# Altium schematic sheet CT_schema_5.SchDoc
size 295 x 165 mm
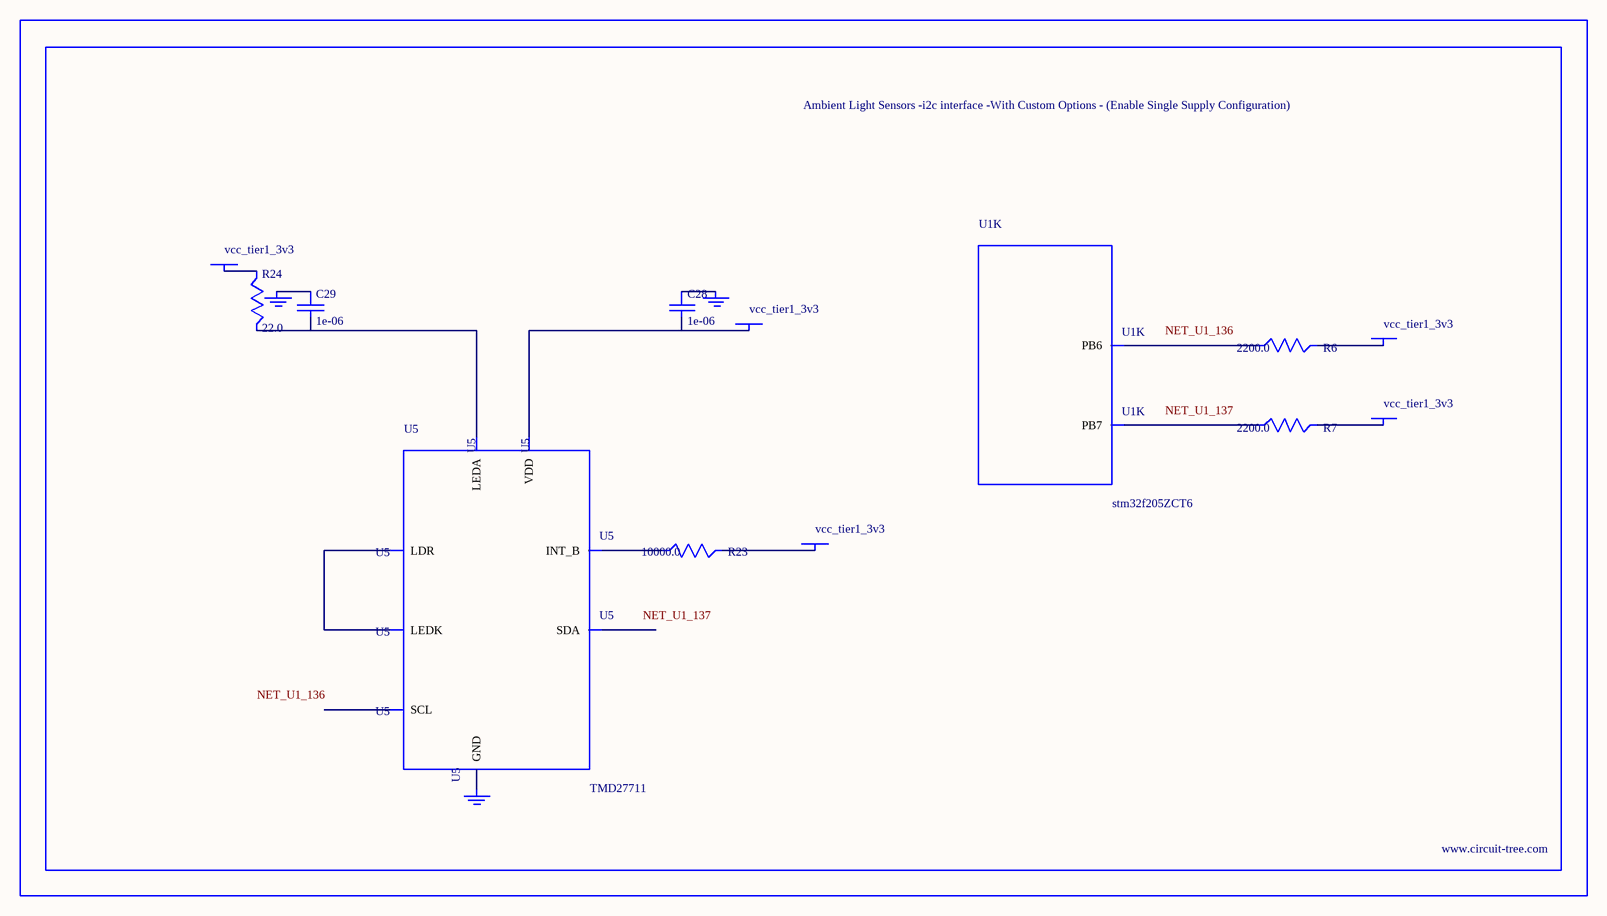
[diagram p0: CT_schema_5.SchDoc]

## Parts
BORDER4  (no value)
C28  1e-06  [C0603]
C29  1e-06  [C0603]
GND_INSTANCE_4_0  (no value)
GND_INSTANCE_4_1  (no value)
GND_INSTANCE_4_2  (no value)
POWER_INSTANCE_4_0  vcc_tier1_3v3
POWER_INSTANCE_4_1  vcc_tier1_3v3
POWER_INSTANCE_4_2  vcc_tier1_3v3
POWER_INSTANCE_4_3  vcc_tier1_3v3
POWER_INSTANCE_4_4  vcc_tier1_3v3
R6  2200.0  [R0603]
R7  2200.0  [R0603]
R23  10000.0  [R0603]
R24  22.0  [R0603]
U1  stm32f205ZCT6  [LQFP144]  (part K of 12)
U5  TMD27711  [SMD-8]

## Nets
NetC28_1: C28.1 GND_INSTANCE_4_0.0(GND)
NetC28_2: C28.2 POWER_INSTANCE_4_0.0(PWR) U5.1(VDD)
NetC29_1: C29.1 GND_INSTANCE_4_1.0(GND)
NetC29_2: C29.2 R24.2 U5.4(LEDA)
NetGND_INSTANCE_4_2_0: GND_INSTANCE_4_2.0(GND) U5.3(GND)
NetPOWER_INSTANCE_4_1_0: POWER_INSTANCE_4_1.0(PWR) R24.1
NetPOWER_INSTANCE_4_2_0: POWER_INSTANCE_4_2.0(PWR) R23.2
NetPOWER_INSTANCE_4_3_0: POWER_INSTANCE_4_3.0(PWR) R6.2
NetPOWER_INSTANCE_4_4_0: POWER_INSTANCE_4_4.0(PWR) R7.2
NetR6_1: R6.1 U1.136(PB6)
NetR7_1: R7.1 U1.137(PB7)
NetR23_1: R23.1 U5.7(INT_B)
NetU5_5: U5.5(LEDK) U5.6(LDR)

Not connected (* = marked no-connect by the designer): U5 2(SCL) 8(SDA)

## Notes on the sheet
- Labels drawn without touching a wire or pin: NET_U1_136, NET_U1_137

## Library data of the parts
BORDER4 = BORDER_PAGE4
C28 C29 = C0603C105K3RACTU
GND_INSTANCE_4_0-GND_INSTANCE_4_2 = GND
POWER_INSTANCE_4_0-POWER_INSTANCE_4_4 = PWR
R6 R7 = RC0603JR-072K2L
R23 = RC0603JR-0710KL
R24 = RC0603JR-0722RL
